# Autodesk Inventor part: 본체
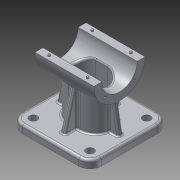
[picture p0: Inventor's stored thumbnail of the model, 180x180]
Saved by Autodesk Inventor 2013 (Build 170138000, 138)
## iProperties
Created: 2015-12
Part Number: 본체
Material: 알루미늄 6061
Document SubType Name: Modeling
Designer: mduedu
Density: 2.71 g/cm^3
Mass: 518.78 g
Surface Area: 500.212 cm^2
Volume: 191.432 cm^3
Author: mduedu
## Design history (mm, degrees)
sketch "스케치1"
  geometry: L1 (-50, -50)-(50, -50); L2 (50, -50)-(50, 50); L3 (50, 50)-(-50, 50); L4 (-50, 50)-(-50, -50); L5 (-50, -50)-(50, 50); L6 (50, -50)-(-50, 50); 2 further points
  constraints: 12 end point, 2 midpoint, 2 parallel, 1 coincident, 1 horizontal, 1 perpendicular
  dimensions: "d154" = 100 distance of L2.end L3.end; "d155" = 100 distance of L3.end L1.start
extrude "돌출1" new body sketch "스케치1" distance "d3" = 10; taper "d4" = 0 deg
sketch "스케치2"
  geometry: C1 r 32.5 at (80, 0); 1 further point
  constraints: 1 centre point, 1 horizontal alignment
  dimensions: "d5" = 65 diameter of C1; "d125" = 80 distance of C1.centre point (0, 0)
extrude "돌출2" join sketch "스케치2" stored distance "d7" = 75; taper "d8" = 0 deg
sketch "스케치3"
  geometry: L1 (-27.5, -20)-(27.5, -20); L2 (27.5, -20)-(27.5, 20); L3 (27.5, 20)-(-27.5, 20); L4 (-27.5, 20)-(-27.5, -20); L5 (-27.5, -20)-(27.5, 20); L6 (27.5, -20)-(-27.5, 20); 1 further point
  constraints: 12 end point, 2 midpoint, 2 parallel, 1 horizontal, 1 perpendicular
  dimensions: "d9" = 55 distance of L2.end L3.end; "d11" = 40 distance of L1.end L2.end
extrude "돌출3" new body sketch "스케치3" stored distance "d12" = 75; taper "d13" = 0 deg
fillet "모깎기1"
fillet "모깎기2"
feature "결합1"
  node "솔리드2"
sketch "스케치4"
  geometry: L1 (-37.5, 47.5)-(37.5, 47.5) reference; L2 (32.5, 47.5)-(39.112, 10); L3 (37.5, 47.5)-(37.5, 112.5) reference; L4 (50, 10)-(-50, 10) reference; 1 further point
  constraints: 2 end point, 2 point on line
  dimensions: "d15" = 5 distance from line of L2.start L3; "d126" = 80 deg angle of L2 L1
feature "리브1" dims "d19" = 1, "d20" = 6, "d21" = 0, "d22" = 0, "d23" = 1, "d24" = 1
feature "리브2" dims "d25" = 1, "d26" = 6, "d27" = 0, "d28" = 0, "d29" = 1, "d30" = 1
fillet "모깎기4" dims "d31" = 2
fillet "모깎기5" dims "d32" = 2
fillet "모깎기6" dims "d33" = 2
fillet "모깎기7" dims "d41" = 14
hole "구멍2" diameter "d44" = 45; stored, may be unused: countersink angle "d48" = 90 deg, drill point angle "d50" = 118 deg; dims "d42" = 10, "d43" = 10, "d45" = 6, "d46" = 4, "d47" = 2, "d49" = 8
sketch "스케치7" dims "d52" = 26.5
  geometry: L1 (0, 0)-(32.5, 0); L2 (0, 0)-(22.981, 22.981); A1 r 32.5 centre (0, 0) between (32.5, 0) and (22.981, 22.981) reference; 3 further points
  constraints: 4 end point, 2 point on circle, 1 coincident, 1 horizontal, 1 point on line, 3 other
  dimensions: "d51" = 45 deg angle of L2 L1
hole "구멍3" sketch "스케치7" at (18.738, 18.738) diameter "d54" = 2.459; stored, may be unused: countersink angle "d58" = 90 deg, drill point angle "d60" = 118 deg; dims "d55" = 8, "d56" = 4, "d57" = 2, "d59" = 10
sketch "스케치9"
  geometry: L1 (-75, 82.5)-(75, 82.5); L2 (75, 82.5)-(75, 0); L3 (75, 0)-(-75, 0); L4 (-75, 0)-(-75, 82.5); C1 r 32.5 at (0, 0) reference; 2 further points
  constraints: 8 end point, 2 parallel, 1 coincident, 1 horizontal, 1 midpoint, 1 perpendicular
  dimensions: "d71" = 50 distance edge to line of C1 L1; "d116" = 150 distance between parallel lines of L2 L4
extrude "돌출5" cut sketch "스케치9" stored distance "d73" = 0; taper "d74" = 0 deg
node "작업 평면1"
sketch "스케치10"
  geometry: L1 (-7.5, 15)-(7.5, 15); L2 (-7.5, -15)-(7.5, -15); A1 r 20 centre (-7.5, 0) between (-7.5, 20) and (-26.977, 4.545) reference; A2 r 20 centre (7.5, 0) between (26.977, 4.545) and (7.5, 20) reference; A3 r 15 centre (-7.5, 0) between (-7.5, 15) and (-7.5, -15); A4 r 15 centre (7.5, 0) between (7.5, -15) and (7.5, 15); 1 further point
  constraints: 7 point on circle, 4 end point, 4 tangent, 3 point on line, 2 centre point, 2 coincident, 1 horizontal
  dimensions: "d77" = 5 radial gap between concentric circles of A3 A1
extrude "돌출6" cut sketch "스케치10" stored distance "d78" = 50; taper "d79" = 0 deg
fillet "모깎기10" dims "d80" = 3
sketch "스케치11"
  geometry: 2 further points
  constraints: 1 coincident
hole "구멍4" sketch "스케치11" at (0, 0) diameter "d81" = 12; stored, may be unused: countersink angle "d85" = 90 deg, drill point angle "d87" = 118 deg; dims "d82" = 8, "d83" = 40, "d84" = 10, "d86" = 10
sketch "스케치12"
  geometry: C1 r 10 at (0, 0); 1 further point
  constraints: 1 centre point, 1 coincident
  dimensions: "d88" = 20 diameter of C1
extrude "돌출7" cut sketch "스케치12" distance "d89" = 5; taper "d90" = 0 deg
chamfer "모따기1" distance "d91" = 1; stored, may be unused: second distance "d92" = 2, angle "d93" = 45 deg
fillet "모깎기11" dims "d94" = 0.5
fillet "모깎기12" dims "d115" = 0.3
sketch "스케치15"
  geometry: L1 (-75, 55)-(-75, 65) reference; L2 (0, 65)-(0, 55) reference; L3 (-75, 60)-(0, 60); C1 r 1.5 at (-62, 60); 1 further point
  constraints: 2 end point, 2 midpoint, 1 centre point, 1 point on line
  dimensions: "d117" = 3 diameter of C1; "d118" = 13 distance from line of C1.centre L1
extrude "돌출8" join sketch "스케치15" distance "d119" = 1.8; taper "d120" = 0 deg
chamfer "모따기2" distance "d121" = 0.5; stored, may be unused: second distance "d122" = 2, angle "d123" = 45 deg
sketch "스케치19"
  geometry: A1 r 14 centre (-36, -36) between (-50, -36) and (-36, -50) reference; A2 r 14 centre (-36, 36) between (-36, 50) and (-50, 36) reference; A3 r 14 centre (36, 36) between (50, 36) and (36, 50) reference; A4 r 14 centre (36, -36) between (36, -50) and (50, -36) reference; 5 further points
  constraints: 4 coincident
hole "구멍9" sketch "스케치19" at (-36, -36), (36, -36), (36, 36), (-36, 36) diameter "d156" = 10; stored, may be unused: countersink angle "d160" = 90 deg, drill point angle "d162" = 0 deg; dims "d157" = 6, "d158" = 4, "d159" = 2, "d161" = 8
node "솔리드1"
sketch "스케치5"
  geometry: L1 (10, 35)-(56.569, 22.522); L2 (10, 20)-(54.383, 20) reference; L3 (10, -50)-(10, 50) reference; A1 r 32.5 centre (80, 0) between (56.569, 22.522) and (54.383, 20) reference; 1 further point
  constraints: 2 end point, 1 point on circle, 1 point on line
  dimensions: "d128" = 15 distance of L1.start L2.start
mirror "대칭1"
mirror "대칭2"
pattern_circular "원형 패턴1" dims angle "d62" = 360 deg
mirror "대칭3"
mirror "대칭5"
mirror "대칭6"
